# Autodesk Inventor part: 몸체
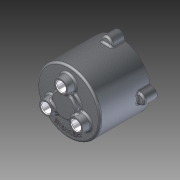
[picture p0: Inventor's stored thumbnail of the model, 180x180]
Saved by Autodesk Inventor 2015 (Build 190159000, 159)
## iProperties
Company: 한국ATC센터
Created: 2014-07
Part Number: 몸체
Document SubType Name: 모델링
Designer: KYOUNG IL JANG
Material: Aluminum 6061
Appearance: Aluminum - Flat
Mass: 473.802 g
Surface Area: 687.659 cm^2
Volume: 175.482 cm^3
Density: 2.7 g/cm^3
Author: KYOUNG IL JANG
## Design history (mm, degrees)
sketch "스케치2"
  geometry: C1 r 50 at (0, 0); 1 further point
  constraints: 1 centre point, 1 coincident
  dimensions: "d9" = 100 diameter of C1
extrude "돌출2" new body sketch "스케치2" distance "d10" = 80; taper "d11" = 0 deg
feature "쉘1" dims "d12" = 5
sketch "스케치3" dims "d13" = 55
  geometry: C1 r 7.5 at (0, 27.5); C2 r 12.5 at (0, 27.5); 2 further points
  constraints: 2 centre point, 2 coincident, 2 vertical alignment, 2 other
  dimensions: "d14" = 15 diameter of C1; "d15" = 25 diameter of C2
extrude "돌출3" join sketch "스케치3" distance "d16" = 12; taper "d17" = -10 deg
hole "구멍2" diameter "d20" = 15; stored, may be unused: countersink angle "d24" = 90 deg, drill point angle "d26" = 118 deg; dims "d18" = 10, "d19" = 10, "d21" = 6, "d22" = 4, "d23" = 2, "d25" = 15
chamfer "모따기1" distance "d27" = 1; stored, may be unused: second distance "d28" = 2, angle "d29" = 45 deg
revolve "회전1" stored, may be unused: angle "d38" = 90 deg
hole "구멍3" diameter "d41" = 15; stored, may be unused: countersink angle "d45" = 90 deg, drill point angle "d47" = 0 deg; dims "d39" = 10, "d40" = 10, "d42" = 6, "d43" = 22, "d44" = 13, "d46" = 15
chamfer "모따기2" distance "d48" = 1; stored, may be unused: second distance "d49" = 2, angle "d50" = 45 deg
fillet "모깎기1" dims "d52" = 3
fillet "모깎기2" dims "d53" = 3, "d72" = 0.2
sketch "스케치5"
  geometry: A1 r 50 centre (0, 0) between (50, 0) and (-8.074, 49.344) reference; A2 r 8.5 centre (0, 52) between (8.074, 49.344) and (-8.074, 49.344); 1 further point
  constraints: 5 point on circle, 1 centre point, 1 horizontal alignment
  dimensions: "d54" = 90 deg dimension on point (0, 0) A2.centre A1.start; "d55" = 52 distance of A2.centre point (0, 0); "d56" = 17 diameter of A2
extrude "돌출4" join sketch "스케치5" distance "d57" = 20; taper "d58" = 0 deg
fillet "모깎기3" dims "d59" = 3
hole "구멍4" diameter "d62" = 4.134; stored, may be unused: countersink angle "d66" = 90 deg, drill point angle "d68" = 118 deg; dims "d60" = 10, "d61" = 10, "d63" = 12, "d64" = 22, "d65" = 13, "d67" = 15
feature "엠보싱1" dims "d74" = 1, "d75" = 0
node "솔리드1"
node "솔리드 본체"
node "곡면 본체"
pattern_circular "원형 패턴1" dims "d31" = 360 deg
pattern_circular "원형 패턴2" dims "d70" = 360 deg
node "솔리드2"
sketch "스케치4"
  geometry: L1 (0, 0)-(0, 88); L2 (0, 70)-(13.16, 70); L3 (-45, 75)-(45, 75) reference; L4 (-50, 80)-(50, 80) reference; L5 (13.16, 70)-(14.5, 75); L6 (20, 80)-(20, 88); L7 (20, 88)-(0, 88); L8 (20, 80)-(14.5, 75)
  constraints: 12 end point, 3 point on line, 2 perpendicular, 1 vertical
  dimensions: "d34" = 40 diameter of L6 L1; "d35" = 105 deg angle of L5 L3; "d36" = 5 distance between parallel lines of L2 L3; "d37" = 8 distance between parallel lines of L7 L4; "d51" = 29 diameter of L5.end L1
sketch "스케치6"
  geometry: C1 r 47 at (0, 0) reference; C2 r 42.5 at (0, 0); 1 further point
  constraints: 1 centre point, 1 coincident, 1 other
  dimensions: "d73" = 85 diameter of C2
